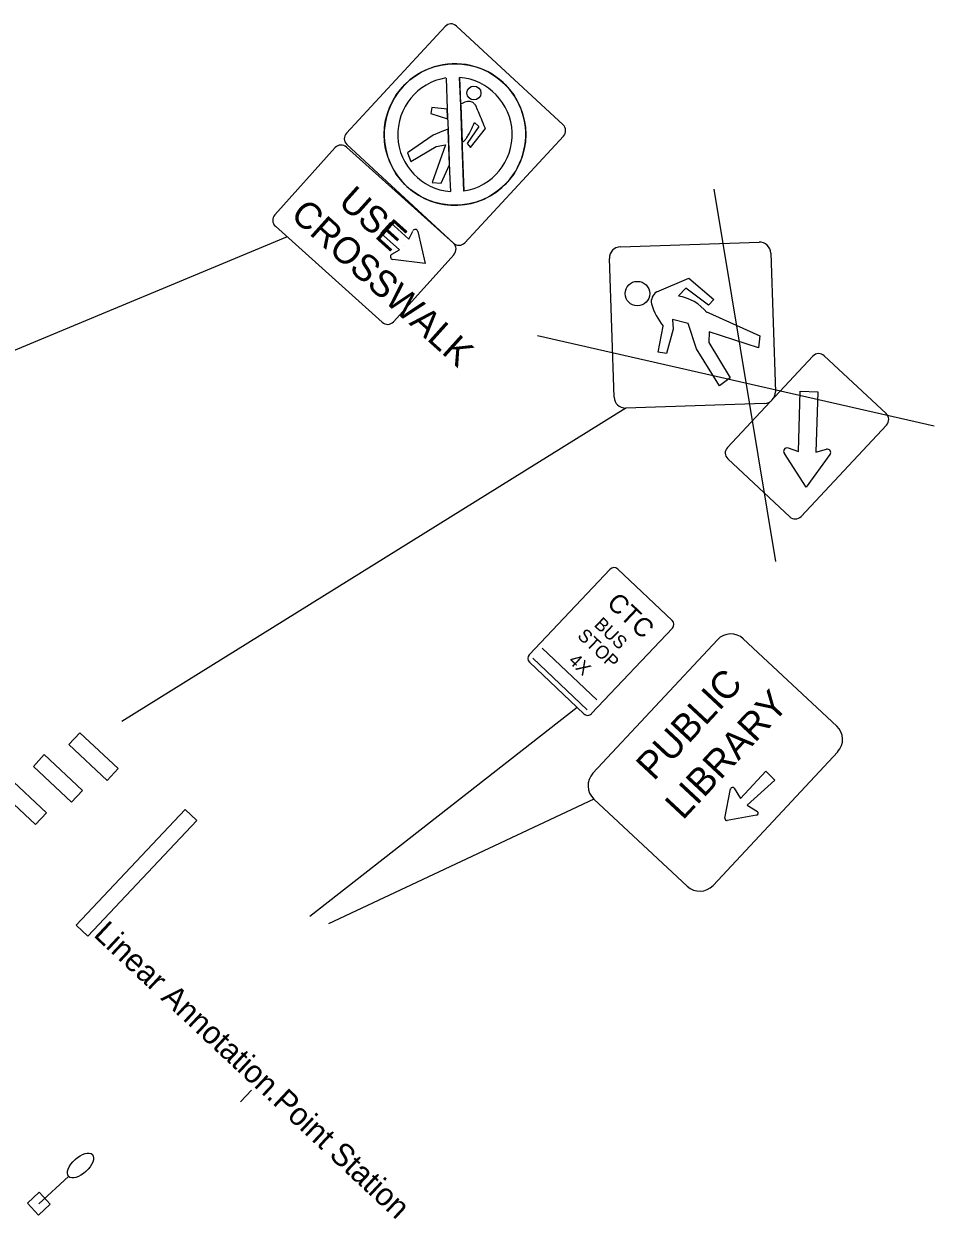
# Model space of a CAD drawing. Extents: x 1470334 to 1481646, y 379063 to 388330.
# Drawn here: x 1480211.9 to 1480324.7, y 379345.8 to 379494 of the extents above; entities that cross this region are included whole.
import ezdxf

# ---------------------------------------------------------------- set-up
doc = ezdxf.new("R2010")
doc.units = 0
for name, color, linetype in [('Default', 7, 'Continuous'), ('GK_Visualization', 7, 'Continuous'), ('SG_X_Poles', 7, 'Continuous'), ('SV_X_Random_Point', 7, 'Continuous'), ('SV_X_Text_Description', 7, 'Continuous'), ('UT_X_Electric_Cells', 7, 'Continuous'), ('UT_X_Water_Cells', 7, 'Continuous')]:
    doc.layers.add(name, color=color, linetype=linetype)

msp = doc.modelspace()

# ---------------------------------------------------------------- linework, layer by layer
at = {"layer": 'Default'}
msp.add_line((1480238.7, 379360.37), (1480240.06, 379361.83), dxfattribs=at)
msp.add_line((1480238.7, 379360.37), (1480240.06, 379361.83), dxfattribs=at)
at = {"layer": 'GK_Visualization'}
for points in [[(1480217.42, 379404.65), (1480218.78, 379406.11), (1480223.53, 379401.66), (1480222.16, 379400.2)], [(1480213.03, 379401.94), (1480214.39, 379403.4), (1480219.14, 379398.96), (1480217.77, 379397.5)], [(1480208.55, 379399.18), (1480209.92, 379400.64), (1480214.66, 379396.19), (1480213.3, 379394.73)]]:
    msp.add_lwpolyline(points, close=True, dxfattribs=at)
at = {"layer": 'SG_X_Poles'}
msp.add_line((1480213.71, 379347.74), (1480217.39, 379351.13), dxfattribs=at)
msp.add_lwpolyline([(1480212.3, 379347.8), (1480213.77, 379349.16), (1480215.12, 379347.68), (1480213.65, 379346.33)], close=True, dxfattribs=at)
msp.add_ellipse((1480218.87, 379352.48), major_axis=(1.47, 1.35), ratio=0.5, dxfattribs=at)
at = {"layer": 'SV_X_Random_Point'}
msp.add_lwpolyline([(1480233.28, 379395.23), (1480219.79, 379380.92), (1480218.35, 379382.28), (1480231.84, 379396.59)], close=True, dxfattribs=at)
at = {"layer": 'SV_X_Text_Description'}
for p, q in [((1480290.28, 379460.75), (1480294.26, 379462.46)), ((1480294.26, 379462.46), (1480297.36, 379459.82)), ((1480293.87, 379461.19), (1480292.98, 379460.24)), ((1480296.69, 379459.1), (1480293.87, 379461.19)), ((1480297.36, 379459.82), (1480296.69, 379459.1)), ((1480296.36, 379458.32), (1480303.07, 379455.3)), ((1480294.18, 379456.84), (1480292.23, 379457.31)), ((1480292.23, 379457.31), (1480292.32, 379456.13)), ((1480295.21, 379453.7), (1480294.18, 379456.84)), ((1480290.44, 379453.28), (1480291.07, 379456.49)), ((1480292.32, 379456.13), (1480291.49, 379453.12)), ((1480296.76, 379455.78), (1480296.72, 379454.46)), ((1480302.89, 379453.83), (1480296.76, 379455.78)), ((1480296.72, 379454.46), (1480299.37, 379450.08)), ((1480303.07, 379455.3), (1480302.89, 379453.83)), ((1480291.49, 379453.12), (1480290.44, 379453.28)), ((1480298.08, 379449.12), (1480295.21, 379453.7)), ((1480299.04, 379441.47), (1480309.63, 379452.79)), ((1480311.05, 379452.83), (1480318.71, 379445.66)), ((1480299.37, 379450.08), (1480298.08, 379449.12)), ((1480307.83, 379440.96), (1480308.07, 379448.43)), ((1480308.07, 379448.43), (1480310.25, 379448.36)), ((1480310.25, 379448.36), (1480310.01, 379440.89)), ((1480286.44, 379446.35), (1480223.98, 379407.51)), ((1480318.76, 379444.24), (1480308.17, 379432.93)), ((1480308.78, 379436.55), (1480306.12, 379440.72)), ((1480306.56, 379441.4), (1480307.83, 379440.96)), ((1480311.75, 379440.6), (1480308.78, 379436.55)), ((1480310.01, 379440.89), (1480311.31, 379441.25)), ((1480311.75, 379440.6), (1480311.75, 379440.6)), ((1480306.76, 379432.88), (1480299.09, 379440.05)), ((1480281.67, 379408.97), (1480274.93, 379415.35)), ((1480282.84, 379410.21), (1480276.1, 379416.59)), ((1480280.43, 379409.24), (1480247.29, 379383.35)), ((1480300.67, 379397.97), (1480303.8, 379401.35)), ((1480300.67, 379397.97), (1480303.8, 379401.35)), ((1480303.8, 379401.35), (1480304.9, 379400.25)), ((1480303.8, 379401.35), (1480304.9, 379400.25)), ((1480298.74, 379395.51), (1480299.42, 379399.14)), ((1480298.74, 379395.51), (1480299.42, 379399.14)), ((1480299.89, 379399.23), (1480300.67, 379397.97)), ((1480299.89, 379399.23), (1480300.67, 379397.97)), ((1480304.9, 379400.25), (1480301.5, 379397.14)), ((1480304.9, 379400.25), (1480301.5, 379397.14)), ((1480282.48, 379397.89), (1480249.6, 379382.41)), ((1480301.95, 379398.31), (1480301.95, 379398.31)), ((1480301.5, 379397.14), (1480302.75, 379396.35)), ((1480301.5, 379397.14), (1480302.75, 379396.35)), ((1480302.66, 379395.88), (1480299.03, 379395.22)), ((1480302.66, 379395.88), (1480299.03, 379395.22))]:
    msp.add_line(p, q, dxfattribs=at)
for points in [[(1480285.78, 379466.34), (1480302.97, 379466.91)], [(1480284.99, 379447.7), (1480284.42, 379464.89)], [(1480304.41, 379465.56), (1480304.98, 379448.36)], [(1480303.63, 379446.92), (1480286.44, 379446.35)], [(1480274.49, 379415.77), (1480284.52, 379426.37)], [(1480285.46, 379426.39), (1480292.2, 379420.01)], [(1480292.22, 379419.07), (1480282.19, 379408.48)], [(1480282.37, 379401.09), (1480297.81, 379417.64)], [(1480301.01, 379417.75), (1480312.6, 379406.94)], [(1480281.25, 379408.45), (1480274.51, 379414.84)], [(1480312.71, 379403.75), (1480297.27, 379387.2)], [(1480294.07, 379387.08), (1480282.48, 379397.89)]]:
    msp.add_lwpolyline(points, dxfattribs=at)
msp.add_circle((1480287.89, 379460.53), 1.52, dxfattribs=at)
for centre, radius, start, end in [((1480285.82, 379464.94), 1.4, 91.9, 181.9), ((1480303.01, 379465.51), 1.4, 1.9, 91.9), ((1480291.1, 379459.5), 1.5, 123.1441, 189.395), ((1480292.09, 379454.66), 5.64, 38.7502, 80.9609), ((1480298.81, 379462.32), 9.69, 198.4411, 216.9317), ((1480310.36, 379452.1), 1, 46.9, 136.9), ((1480303.58, 379448.32), 1.4, 271.9, 1.9), ((1480286.39, 379447.75), 1.4, 181.9, 271.9), ((1480318.03, 379444.93), 1, 316.9, 46.9), ((1480299.77, 379440.78), 1, 136.9, 226.9), ((1480306.42, 379441), 0.417, 70.9541, 223.1683), ((1480311.42, 379440.84), 0.417, 323.5699, 105.3633), ((1480307.44, 379433.61), 1, 226.9, 316.9), ((1480285, 379425.91), 0.663, 46.5645, 136.5645), ((1480291.74, 379419.53), 0.663, 316.5645, 46.5645), ((1480299.47, 379416.1), 2.26, 46.9869, 136.9869), ((1480274.97, 379415.32), 0.663, 136.5645, 226.5645), ((1480281.71, 379408.93), 0.663, 226.5645, 316.5645), ((1480311.05, 379405.29), 2.26, 316.9869, 46.9869), ((1480284.03, 379399.55), 2.26, 136.9869, 226.9869), ((1480299.67, 379399.09), 0.253, 31.8379, 169.3113), ((1480299.67, 379399.09), 0.253, 31.8379, 169.3113), ((1480302.61, 379396.13), 0.253, 280.317, 57.7904), ((1480302.61, 379396.13), 0.253, 280.317, 57.7904), ((1480298.99, 379395.47), 0.253, 170.7205, 278.9078), ((1480298.99, 379395.47), 0.253, 170.7205, 278.9078), ((1480295.61, 379388.74), 2.26, 226.9869, 316.9869)]:
    msp.add_arc(centre, radius, start, end, dxfattribs=at)
at = {"layer": 'UT_X_Electric_Cells'}
for p, q in [((1480297.36, 379473.48), (1480304.99, 379427.33)), ((1480275.49, 379455.32), (1480324.65, 379444.13))]:
    msp.add_line(p, q, dxfattribs=at)
at = {"layer": 'UT_X_Water_Cells'}
for p, q in [((1480265.85, 379487.32), (1480266.39, 379473.24)), ((1480262.4, 379483.58), (1480262.3, 379482.87)), ((1480262.4, 379483.58), (1480262.3, 379482.87)), ((1480264.32, 379483.38), (1480262.4, 379483.58)), ((1480264.32, 379483.38), (1480262.4, 379483.58)), ((1480265.98, 379484), (1480265.99, 379483.85)), ((1480265.99, 379483.85), (1480266.16, 379479.3)), ((1480262.3, 379482.87), (1480264.36, 379482.21)), ((1480262.3, 379482.87), (1480264.36, 379482.21)), ((1480264.36, 379482.21), (1480264.35, 379482.45)), ((1480263.87, 379480.72), (1480262.56, 379480.18)), ((1480263.87, 379480.72), (1480262.56, 379480.18)), ((1480264.42, 379480.91), (1480263.87, 379480.72)), ((1480264.42, 379480.91), (1480263.87, 379480.72)), ((1480264.42, 379480.83), (1480264.42, 379480.91)), ((1480264.59, 379476.47), (1480264.42, 379480.83)), ((1480268.22, 379481.23), (1480266.77, 379479.12)), ((1480268.22, 379481.23), (1480266.77, 379479.12)), ((1480267.2, 379478.65), (1480269.07, 379481)), ((1480267.2, 379478.65), (1480269.07, 379481)), ((1480267.71, 379481.75), (1480268.22, 379481.23)), ((1480267.71, 379481.75), (1480268.22, 379481.23)), ((1480269.07, 379481), (1480269.05, 379481.01)), ((1480269.07, 379481), (1480269.05, 379481.01)), ((1480262.56, 379480.18), (1480259.38, 379477.98)), ((1480262.56, 379480.18), (1480259.38, 379477.98)), ((1480266.77, 379479.12), (1480267.2, 379478.65)), ((1480266.77, 379479.12), (1480267.2, 379478.65)), ((1480259.38, 379477.98), (1480259.79, 379476.91)), ((1480259.38, 379477.98), (1480259.79, 379476.91)), ((1480259.79, 379476.91), (1480262.95, 379478.78)), ((1480259.79, 379476.91), (1480262.95, 379478.78)), ((1480264.09, 379478.96), (1480262.47, 379474.31)), ((1480264.09, 379478.96), (1480262.47, 379474.31)), ((1480262.95, 379478.78), (1480264.09, 379478.96)), ((1480262.95, 379478.78), (1480264.09, 379478.96)), ((1480263.58, 379474.2), (1480264.59, 379476.47)), ((1480263.58, 379474.2), (1480264.59, 379476.47)), ((1480262.47, 379474.31), (1480263.58, 379474.2)), ((1480262.47, 379474.31), (1480263.58, 379474.2)), ((1480256.11, 379468.03), (1480257.28, 379469.34)), ((1480257.28, 379469.34), (1480259.57, 379467.28)), ((1480244.47, 379467.58), (1480193.15, 379446.17)), ((1480259.57, 379467.28), (1480259.58, 379467.27)), ((1480259.58, 379467.27), (1480260.04, 379468.29)), ((1480260.69, 379468.23), (1480261.6, 379464.27)), ((1480257.44, 379465.4), (1480258.41, 379465.96)), ((1480259.07, 379466.54), (1480259.07, 379466.54)), ((1480261.6, 379464.27), (1480257.57, 379464.76))]:
    msp.add_line(p, q, dxfattribs=at)
for points in [[(1480264.05, 379493.63), (1480251.82, 379480.43)], [(1480278.67, 379481.46), (1480265.46, 379493.69)], [(1480264.17, 379487.25), (1480264.32, 379483.42), (1480264.36, 379482.45), (1480264.35, 379482.45)], [(1480265.99, 379483.85), (1480265.85, 379487.32)], [(1480266.39, 379473.24), (1480266.18, 379478.83), (1480266.18, 379478.83), (1480266.18, 379478.83), (1480265.99, 379483.85), (1480265.99, 379483.85)], [(1480265.99, 379483.85), (1480265.99, 379483.85)], [(1480264.35, 379482.45), (1480264.32, 379483.38), (1480264.32, 379483.38)], [(1480264.35, 379482.45), (1480264.42, 379480.83), (1480264.62, 379475.59), (1480264.72, 379473.18)], [(1480266.5, 379466.84), (1480278.73, 379480.05)], [(1480250.45, 379478.62), (1480242.95, 379470.28)], [(1480265.08, 379466.78), (1480251.84, 379478.69)], [(1480251.88, 379479.01), (1480265.08, 379466.78)], [(1480243.02, 379468.89), (1480256.26, 379456.98)], [(1480258.4, 379465.97), (1480256.11, 379468.03)], [(1480257.66, 379457.05), (1480265.16, 379465.39)]]:
    msp.add_lwpolyline(points, dxfattribs=at)
for centre, radius in [((1480265.28, 379480.25), 8.77), ((1480267.63, 379485.39), 0.864)]:
    msp.add_circle(centre, radius, dxfattribs=at)
for centre, radius, start, end in [((1480264.79, 379492.96), 1, 47.1998, 137.1998), ((1480265.28, 379480.25), 8.77, 317.1998, 137.1998), ((1480265.28, 379480.25), 7.09, 99.0477, 265.4477), ((1480265.28, 379480.25), 7.09, 99.0477, 265.4477), ((1480265.28, 379480.25), 7.09, 279.0188, 85.3711), ((1480265.28, 379480.25), 7.09, 279.0188, 85.3711), ((1480265.28, 379480.25), 8.77, 137.1998, 317.1998), ((1480266.23, 379482.34), 1.54, 99.2749, 99.3281), ((1480277.99, 379480.73), 1, 317.1998, 47.1998), ((1480252.56, 379479.75), 1, 137.1998, 227.1998), ((1480251.18, 379477.96), 0.989, 48.0309, 138.0309), ((1480243.68, 379469.62), 0.989, 138.0309, 228.0309), ((1480260.36, 379468.15), 0.342, 12.9516, 155.6687), ((1480265.76, 379467.52), 1, 227.1998, 317.1998), ((1480264.42, 379466.05), 0.989, 318.0309, 48.0309), ((1480257.61, 379465.1), 0.342, 120.3931, 263.1101), ((1480256.92, 379457.71), 0.989, 228.0309, 318.0309)]:
    msp.add_arc(centre, radius, start, end, dxfattribs=at)
for points in [[(1480269.05, 379481.01), (1480268.67, 379481.9), (1480268.08, 379483.31), (1480267.87, 379483.82), (1480267.77, 379483.96), (1480267.64, 379484.08), (1480267.35, 379484.35), (1480266.66, 379484.34), (1480266.24, 379484.13), (1480265.98, 379484)], [(1480269.05, 379481.01), (1480268.67, 379481.9), (1480268.08, 379483.31), (1480267.87, 379483.82), (1480267.77, 379483.96), (1480267.64, 379484.08), (1480267.35, 379484.35), (1480266.66, 379484.34), (1480266.24, 379484.13), (1480265.98, 379484)], [(1480266.16, 379479.3), (1480266.23, 379479.33), (1480266.42, 379479.44), (1480266.71, 379479.8), (1480266.93, 379480.16), (1480267.27, 379480.83), (1480267.5, 379481.3), (1480267.71, 379481.75)], [(1480266.16, 379479.3), (1480266.23, 379479.33), (1480266.42, 379479.44), (1480266.71, 379479.8), (1480266.93, 379480.16), (1480267.27, 379480.83), (1480267.5, 379481.3), (1480267.71, 379481.75)]]:
    msp.add_open_spline(points, degree=3, dxfattribs=at)

# ---------------------------------------------------------------- texts
at = {"layer": 'Default'}
msp.add_text('Linear Annotation.Point Station', height=2.8, rotation=316.886, dxfattribs=at).set_placement((1480220.37, 379380.96))
msp.add_text('Linear Annotation.Point Station', height=2.8, rotation=316.886, dxfattribs=at).set_placement((1480220.37, 379380.96))
at = {"layer": 'SV_X_Text_Description'}
for s, height, rotation, p in [('CTC', 2.321, 316.5645, (1480283.96, 379422.01)), ('BUS', 1.625, 316.5645, (1480282.43, 379419.39)), ('STOP', 1.625, 316.5645, (1480280.35, 379418)), ('4X', 1.625, 316.5645, (1480279.24, 379414.91)), ('PUBLIC', 3.395, 46.9869, (1480289.91, 379400.05)), ('LIBRARY', 3.395, 46.9869, (1480293.51, 379395.19))]:
    msp.add_text(s, height=height, rotation=rotation, dxfattribs=at).set_placement(p)
at = {"layer": 'UT_X_Water_Cells'}
for s, p in [('USE', (1480250.67, 379471.67)), ('CROSSWALK', (1480244.75, 379470.07))]:
    msp.add_text(s, height=3.296, rotation=318.0309, dxfattribs=at).set_placement(p)

doc.saveas('drawing.dxf')
